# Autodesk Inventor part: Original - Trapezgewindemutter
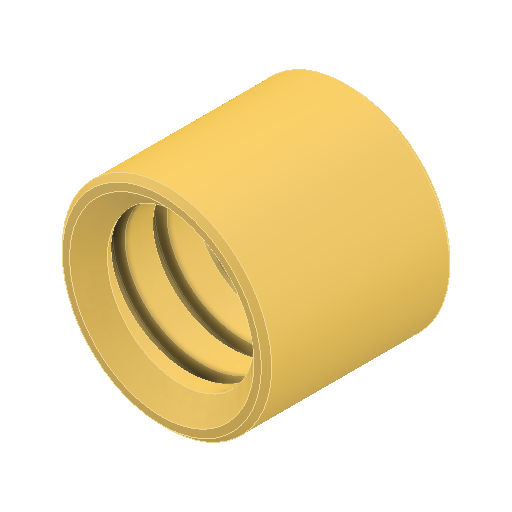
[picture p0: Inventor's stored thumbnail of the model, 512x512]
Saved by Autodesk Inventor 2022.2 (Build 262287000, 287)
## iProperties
Created: 2024-09
Part Number: Original - Trapezgewindemutter
Material: Generico
Document SubType Name: Modeling
Designer: 18907419
Density: 1 g/cm^3
Appearance: Default
Author: 18907419
Revision Number: ANY
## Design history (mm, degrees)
feature "Schnitt-Rotation1"
node "Solido1"
